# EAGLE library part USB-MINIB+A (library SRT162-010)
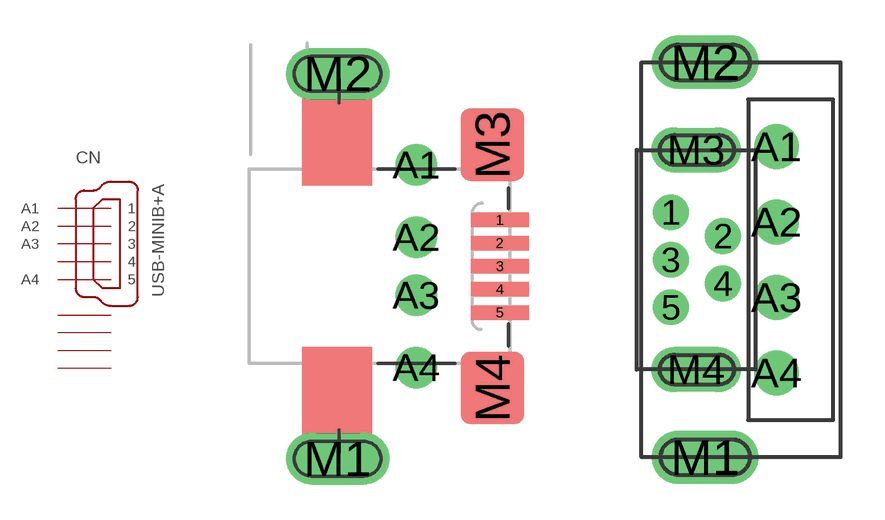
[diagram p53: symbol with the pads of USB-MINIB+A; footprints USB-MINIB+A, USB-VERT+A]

Designator prefix CN

## USB-MINIB+A  [USB-MINIB+A]
1  1  in
2  2  in
3  3  in
4  4  in
5  5  in
A1  A1  in
A2  A2  in
A3  A3  in
A4  A4  in
M1  GND  pwr
M2  GND  pwr
M3  GND  pwr
M4  GND  pwr

## USB-MINIB+AV  [USB-VERT+A]
Pads as for USB-MINIB+A

## Footprint USB-MINIB+A (pad centres in mm)
smd 2 x 0.5: 1 2.25,1.6; 2 2.25,0.8; 3 2.25,0; 4 2.25,-0.8; 5 2.25,-1.6
drill 0.93 round: A1 -0.635,3.5; A2 -0.635,1; A3 -0.635,-1; A4 -0.635,-3.5
drill 1.2 long: M1 -3.345,-6.65; M2 -3.345,6.65
smd 2.2 x 2.5: M3 2,4.2; M4 2,-4.2

## Footprint USB-VERT+A (pad centres in mm)
drill 0.7 pad 1.1 round: 1 -3.56,1.6; 2 -1.81,0.8; 3 -3.56,0; 4 -1.81,-0.8; 5 -3.56,-1.6
drill 1 round: A1 0,3.81; A2 0,1.27; A3 0,-1.27; A4 0,-3.81
drill 1.2 long: M1 -2.4,-6.65; M2 -2.4,6.65
drill 1 long: M3 -2.71,3.7; M4 -2.71,-3.7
